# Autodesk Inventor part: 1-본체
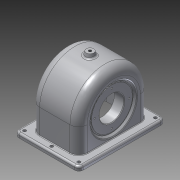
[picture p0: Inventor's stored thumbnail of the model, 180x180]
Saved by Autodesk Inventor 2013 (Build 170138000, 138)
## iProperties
Created: 2015-09
Part Number: 1-본체
Material: 알루미늄 6061
Document SubType Name: Modeling
Designer: Administrator
Density: 2.40731 g/cm^3
Mass: 609.629 g
Surface Area: 905.095 cm^2
Volume: 253.241 cm^3
Author: Administrator
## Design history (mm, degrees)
sketch "스케치1"
  geometry: L1 (-52, 70)-(52, 70); L2 (52, 70)-(52, -70); L3 (52, -70)-(-52, -70); L4 (-52, -70)-(-52, 70); 3 further points
  constraints: 8 end point, 2 midpoint, 2 parallel, 1 horizontal, 1 horizontal alignment, 1 perpendicular, 1 vertical alignment
  dimensions: "d0" = 104 distance between parallel lines of L2 L4; "d2" = 140 distance between parallel lines of L3 L1
extrude "돌출1" new body sketch "스케치1" distance "d3" = 7; taper "d4" = 0 deg
node "작업 평면3"
sketch "스케치4"
  geometry: L1 (70, 7)-(-70, 7) reference; L2 (-57, 7)-(57, 7); L3 (57, 7)-(57, 104); L4 (57, 104)-(-57, 104); L5 (-57, 104)-(-57, 7); 2 further points
  constraints: 8 end point, 2 parallel, 1 horizontal, 1 midpoint, 1 perpendicular, 1 point on line, 1 vertical alignment
  dimensions: "d11" = 97 distance between parallel lines of L4 L2; "d13" = 114 distance between parallel lines of L3 L5
extrude "돌출2" join sketch "스케치4" stored distance "d14" = 77; taper "d15" = 0 deg
feature "쉘1" dims "d16" = 5, "d17" = 7
fillet "모깎기1" dims "d18" = 57
fillet "모깎기2" dims "d19" = 51
node "작업 평면5"
sketch "스케치6"
  geometry: C1 r 6 at (0, 0); 1 further point
  constraints: 1 centre point, 1 coincident
  dimensions: "d22" = 12 diameter of C1
extrude "돌출3" join sketch "스케치6" stored distance "d24" = 77; taper "d25" = 0 deg
sketch "스케치7"
  geometry: 3 further points
  constraints: 1 coincident
hole "구멍1" sketch "스케치7" at (0, 0) diameter "d27" = 4.459; stored, may be unused: countersink angle "d31" = 90 deg, drill point angle "d33" = 0 deg; dims "d28" = 6, "d29" = 4, "d30" = 2, "d32" = 8
sketch "스케치10"
  geometry: C1 r 31 at (47, 0); A1 r 57 centre (47, 0) between (47, -57) and (47, 57) reference; 1 further point
  constraints: 1 centre point, 1 coincident
  dimensions: "d36" = 62 diameter of C1
extrude "돌출4" join sketch "스케치10" distance "d39" = 10; taper "d40" = 0 deg
sketch "스케치11"
  geometry: C1 r 31 at (0, 0) reference; C2 r 20 at (0, 0); 1 further point
  constraints: 1 centre point, 1 coincident
  dimensions: "d41" = 40 diameter of C2
extrude "돌출5" cut sketch "스케치11" stored distance "d43" = 0; taper "d44" = 0 deg
sketch "스케치12"
  geometry: C1 r 20 at (0, 0) reference; 2 further points
  constraints: 1 horizontal alignment
  dimensions: "d45" = 24 distance of point (24, 0) C1.centre
hole "구멍2" sketch "스케치12" at (24, 0) diameter "d46" = 2.459; stored, may be unused: countersink angle "d50" = 90 deg, drill point angle "d52" = 118 deg; dims "d47" = 6, "d48" = 4, "d49" = 2, "d51" = 8
sketch "스케치14"
  geometry: C1 r 35 at (-47, 0); A1 r 57 centre (-47, 0) between (-47, 57) and (-47, -57) reference; 1 further point
  constraints: 1 centre point, 1 coincident
  dimensions: "d56" = 70 diameter of C1
extrude "돌출6" cut sketch "스케치14" distance "d58" = 4; taper "d59" = 0 deg
feature "면 기울기3" dims angle "d151" = 15 deg
feature "면 기울기2" dims angle "d60" = 35 deg
sketch "스케치16"
  geometry: C1 r 35 at (0, 0) reference; C2 r 33 at (0, 0); 1 further point
  constraints: 1 centre point, 1 coincident
  dimensions: "d63" = 66 diameter of C2
extrude "돌출7" join sketch "스케치16" distance "d65" = 1; taper "d66" = 0 deg
chamfer "모따기1" distance "d71" = 1; stored, may be unused: second distance "d72" = 2, angle "d73" = 45 deg
node "작업 평면6"
sketch "스케치8"
  geometry: L1 (-38.5, 47)-(-38.5, 104) reference; L2 (-38.5, 47)-(-38.5, 7) reference; L3 (-33.5, 48)-(-33.5, 0) reference; L4 (-33.5, 48)-(-33.5, 99) reference; L5 (33.5, 99)-(33.5, 48) reference; L6 (33.5, 0)-(33.5, 48) reference; L7 (38.5, 7)-(38.5, 47) reference; L8 (38.5, 104)-(38.5, 47) reference; L9 (33.5, 48)-(19.5, 48); L10 (19.5, 48)-(19.5, 76); L11 (19.5, 76)-(33.5, 87.747); 1 further point
  constraints: 6 end point, 2 perpendicular, 1 point on line
  dimensions: "d82" = 56 diameter of L10.end L9; "d84" = 14 distance between parallel lines of L5 L10; "d86" = 50 deg angle of L11 L10
revolve "회전1" sketch "스케치8" stored, may be unused: angle "d87" = 90 deg
sketch "스케치19"
  geometry: C1 r 33 at (0, 0) reference; C2 r 20 at (0, 0); 1 further point
  constraints: 1 centre point, 1 coincident
  dimensions: "d88" = 40 diameter of C2
extrude "돌출9" cut sketch "스케치19" stored distance "d90" = 0; taper "d91" = 0 deg
sketch "스케치20"
  geometry: C1 r 20 at (0, 0) reference; 2 further points
  constraints: 1 horizontal alignment
  dimensions: "d92" = 28 distance of C1.centre point (-28, 0)
hole "구멍4" sketch "스케치20" at (-28, 0) diameter "d93" = 2.459; stored, may be unused: countersink angle "d97" = 90 deg, drill point angle "d99" = 118 deg; dims "d94" = 7, "d95" = 4, "d96" = 2, "d98" = 9
fillet "모깎기3" dims "d103" = 3
fillet "모깎기4" dims "d104" = 14
fillet "모깎기5" dims "d105" = 9
fillet "모깎기6" dims "d106" = 1
fillet "모깎기7" dims "d107" = 7
fillet "모깎기9" dims "d111" = 0.5
chamfer "모따기2" distance "d112" = 1; stored, may be unused: second distance "d113" = 2, angle "d114" = 45 deg
fillet "모깎기10" dims "d115" = 3
sketch "스케치22"
  geometry: L1 (63, 0)-(63, 39) reference; L2 (-20.5, 47)-(69.5, 47) reference; 2 further points
  constraints: 1 other
  dimensions: "d116" = 38.5 distance from line of L1 point (24.5, 17); "d117" = 30 distance from line of L2 point (24.5, 17)
feature "엠보싱1" sketch "스케치22" dims "d118" = 0.5, "d119" = 0
fillet "모깎기11" dims "d120" = 3
sketch "스케치23"
  geometry: C1 r 2.5 at (-44, 62); 1 further point
  constraints: 1 centre point
  dimensions: "d121" = 44 horizontal distance of point (0, 0) C1.centre; "d122" = 62 vertical distance of C1.centre point (0, 0); "d123" = 5 diameter of C1
extrude "돌출10" cut sketch "스케치23" stored distance "d124" = 0; taper "d125" = 0 deg
sketch "스케치25"
  geometry: C1 r 2.5 at (0, 62); 1 further point
  constraints: 1 centre point, 1 vertical alignment
  dimensions: "d138" = 5 diameter of C1; "d140" = 62 distance of C1.centre point (0, 0)
extrude "돌출11" cut sketch "스케치25" stored distance "d141" = 0; taper "d142" = 0 deg
chamfer "모따기3" distance "d146" = 1; stored, may be unused: second distance "d147" = 2, angle "d148" = 45 deg
fillet "모깎기12" dims "d149" = 3
fillet "모깎기13" dims "d152" = 0.5
node "솔리드1"
pattern_circular "원형 패턴1" dims angle "d54" = 360 deg
pattern_circular "원형 패턴2" dims angle "d101" = 360 deg
mirror "대칭1"
mirror "대칭2"
pattern_linear "직사각형 패턴3" dims "d145" = 124
other parameters: "d10" = 90 deg, "d34" = 90 deg
